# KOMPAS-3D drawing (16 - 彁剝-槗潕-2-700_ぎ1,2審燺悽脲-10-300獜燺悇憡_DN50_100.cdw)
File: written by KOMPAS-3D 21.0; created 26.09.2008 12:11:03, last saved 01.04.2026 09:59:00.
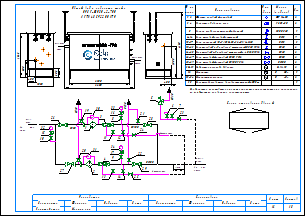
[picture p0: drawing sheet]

Sheets 1-2: A3, landscape

Document properties: Наименование: Макро:21; Автор: RaskoAdmin; Форматы листов документа: 2xA3; Полное имя файла: \\UR38nt01\Departments\КТО\КБ ПУРДГ\Заявки\Прайс-лист на типовые шкафы ГРПШ\ПРДГ_стандарт_20_03_2026\ПРДГ с РДСК\ПРДГ-ШУЭО-2-700_до1,2МПа_Рвых-10-300кПа_РДСК_DN50_100.cdw

Title block, sheet 1: Наименование: Пункт учета газа / ПУГ-Ш-400-Р / ЛГТИ.485922.001ТУ; designation: ЛГТИ.03.4411141; sheet number: 1; Количество листов документа: 2; organisation: ООО "ЭЛЬСТЕР Газэлектроника"; Форматы листов документа: A3; stored path: C:\Рабочие документы\Компас\ПУГ\Схема.cdw; Разработал: Устинов; Проверил: Кошкин; Утвердил: Кошкин
Title block, sheet 2: sheet number: 2; stored path: D:\Рабочие документы\Заявки\ПУРДГ\ПУРДГ-ШУЭО-2-100-Р 4411220.cdw; designation, second copy: ЛГТИ.03.4411141-

Views: Вид 1, Вид 2
Referenced files: wcvoit.frw
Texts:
  Normal
  Вход
  газа
  PDI
  Выход
  Р=     кПа
  DN100
  DN50
  DN20
  Импульс DN20
  ≥5DN
  HYSWLongFangSong
  № на
  схеме
  Усл.
  обозн.
  Марка
  (модель)
  Кол.
  Фильтр газовый фланцевый
  ФГ 16-50
  Регулятор давления газа
  РДCК-50
  Клапан предохранительный сбросной
  КПС DN20
  Кран шаровой газовый латунный
  DN15
  Кран кнопочный VE-РАСКО-НЗ-1,6-G1/2-М20
  Кран шаровой "под приварку" штуцерный DN20 PN16
  Кран шаровой "под приварку" штуцерный п/п DN20 PN16
  Кран шаровой фланцевый DN50 PN16
  Кран шаровой фланцевый DN100 PN16
  Индикатор перепада давления
  Delta 15
  Манометр
  Манометр-напоромер
  Электрообогреватель взрывозащищенный 400Вт
  0...     МПа
  0...     кПа
  Общий вид и габариты шкафа
  ПРДГ-ШУЭО-2-700
  Выход газа
  Вход газа
  Схема открывания дверей
  Р=        МПа
  logo-rasko-ge.png
  Предприятие изготовитель может заменять комплектующие на аналогичные,
  не ухудшающие заявленных характеристик.
  Должность
  Конструктор
  Фамилия
  Подпись
  Дата
  Согласовано
  Максимкин
  Лист
  Листов
  POLYLINE_STYLE_0.18_RGB_0_0_0
  POLYLINE_STYLE_0.50_RGB_0_0_0
  POLYLINE_STYLE_0.34_RGB_0_0_0
  PHANTOM_RGB_0_0_0_SC_1_THICK_0.18
  K5LT_THIN_RGB_0_0_0_THICK_0.18
  K5LT32769_RGB_0_0_0_THICK_0.18
  K5LT12_RGB_0_0_0_SC_1_THICK_0.18
  K5LT_DASHED_RGB_0_0_0_SC_1_THICK_0.18
  ACISOTGL_RGB_0_0_0_SC_0.8_THICK_0.25
  CONTINUOUS_RGB_0_127_31_THICK_0.3
  CONTINUOUS_RGB_0_0_255_THICK_0.35
  CONTINUOUS_RGB_255_0_0_THICK_0.35
  POLYLINE_STYLE_0.25_RGB_0_0_0
  CONTINUOUS_RGB_0_0_0_THICK_0.5
  POLYLINE_STYLE_0.35_RGB_0_0_255
  CONTINUOUS_RGB_0_0_0_THICK_0.4
  CONTINUOUS_RGB_0_0_0_THICK_0.35
  Без оформления
Dimensions and other numbers on the sheet: 1; 2; 3; 4; 5; 10; 27; 28; 29; 23; 8; 12; 19; 20; 21; 22; 25; 24; 30; 31; 15; 16; 26; 6; 7; 11; 14; 13; 33; 1, 2; 3, 4; 6-14; 9; 15-17; 18-23; 24-25; 26-27; 28-29; 30-31; 32; 33-34; 35; 400; 1050; 500; 305; 2300; 1565; 2600; 17; 34; 1000; 4130; 18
